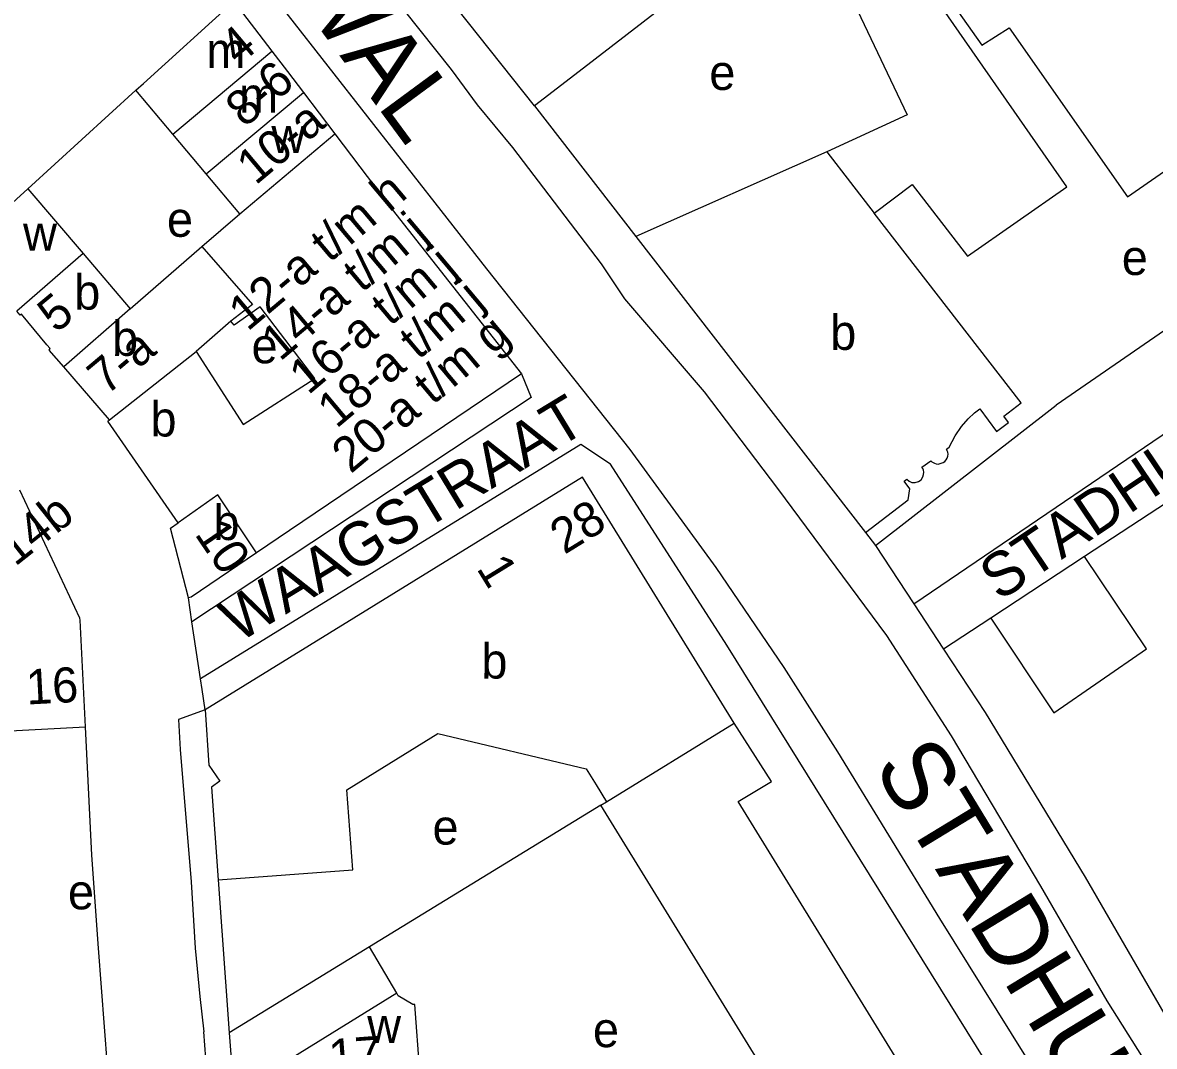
# Model space of a CAD drawing. Extents: x 160673 to 161924, y 382258 to 384145.
# Drawn here: x 161318.4 to 161447.5, y 382888.8 to 383005.6 of the extents above; entities that cross this region are included whole.
import ezdxf

# ---------------------------------------------------------------- set-up
doc = ezdxf.new("R2010")
doc.units = 0
for name, color, linetype in [('BLT_Basislijn', 7, 'Continuous'), ('BLT_Bebouwing', 7, 'Continuous'), ('BLT_Centroide', 7, 'Continuous'), ('BLT_Huisnummer', 7, 'Continuous'), ('BLT_Huisnummer_ tussenligend', 7, 'Continuous'), ('BLT_Huisnummer_reeks', 7, 'Continuous'), ('BLT_Onderverdeling_panden', 7, 'Continuous'), ('BLT_Straatnaam', 7, 'Continuous'), ('BLT_Straatnaam_hoofdweg', 7, 'Continuous')]:
    doc.layers.add(name, color=color, linetype=linetype)

msp = doc.modelspace()

# ---------------------------------------------------------------- linework, layer by layer
at = {"layer": 'BLT_Basislijn'}
for p, q in [((161376.8, 382996.09), (161367.97, 383007.22)), ((161420.08, 382939.26), (161492.74, 382988.68)), ((161415.71, 382945.94), (161436.33, 382961.95)), ((161414.58, 382947.4), (161415.71, 382945.94)), ((161415.71, 382945.94), (161420.08, 382939.26)), ((161439.55, 382944.66), (161428.86, 382937.65)), ((161337.74, 382937.22), (161337.33, 382939.95)), ((161420.08, 382939.26), (161423.46, 382934.11)), ((161338.72, 382930.7), (161337.74, 382937.22)), ((161428.86, 382937.65), (161423.46, 382934.11)), ((161338.9, 382929.5), (161338.72, 382930.7)), ((161339.25, 382927.17), (161338.9, 382929.5)), ((161384.39, 382916.3), (161357.99, 382900.14)), ((161340.74, 382907.78), (161342, 382890.33)), ((161357.99, 382900.14), (161342, 382890.33)), ((161361.1, 382894.85), (161357.99, 382900.14)), ((161338.66, 382894.47), (161339.09, 382890.45)), ((161339.67, 382883.24), (161339.09, 382890.45)), ((161342, 382890.33), (161342.35, 382885.48))]:
    msp.add_line(p, q, dxfattribs=at)
for points in [[(161327.06, 383051.02), (161340.89, 383033.78), (161345.71, 383027.39), (161367.29, 383000.24), (161370.29, 382996.19), (161374.32, 382991.32), (161384.42, 382978.06), (161387.07, 382974.07)], [(161319.1, 383044.02), (161329.09, 383031.39), (161344.2, 383012.2), (161371.35, 382977.49), (161387.69, 382956.87)], [(161415.57, 382983.83), (161419.89, 382987.09), (161426.21, 382978.94), (161437.55, 382986.83), (161417.15, 383016.16), (161416.86, 383017.52), (161417.04, 383018.52), (161417.62, 383019.45), (161418.51, 383020.31), (161420, 383021.17)], [(161407.61, 383019.7), (161419.32, 382995.05), (161410.14, 382990.82)], [(161400.65, 383014.5), (161381.9, 383000), (161376.8, 382996.09)], [(161454.27, 382992.55), (161467.31, 383001.83), (161476.08, 382989.35), (161436.33, 382961.95)], [(161376.8, 382996.09), (161388.37, 382981.18)], [(161387.07, 382974.07), (161396.16, 382963.45), (161404.53, 382952.42), (161416.98, 382935.67), (161424.33, 382924.23), (161434.54, 382907.07)], [(161484.4, 382975.08), (161476.64, 382969.98), (161470.56, 382965.68), (161466.56, 382963.16), (161452.07, 382953.28), (161449.02, 382950.87), (161439.55, 382944.66)], [(161375.34, 382965.52), (161376.43, 382962.82), (161337.74, 382937.22)], [(161434.31, 382877.39), (161398.76, 382934.55), (161385.47, 382955.19), (161382.08, 382957.45), (161338.72, 382930.7)], [(161387.69, 382956.87), (161397.49, 382943.43), (161405.24, 382931.99), (161411.37, 382922.39), (161423, 382903.39), (161434.44, 382885), (161449.34, 382860.28)], [(161428.86, 382937.65), (161436.04, 382926.83), (161446.6, 382934.15), (161439.55, 382944.66)], [(161423.46, 382934.11), (161428.21, 382926.88), (161439.64, 382908.09)], [(161339.25, 382927.17), (161336.21, 382926.06), (161336.41, 382922.64), (161337.67, 382907.55), (161338.12, 382900), (161338.66, 382894.47)], [(161328.11, 382886.52), (161327.08, 382900), (161326.32, 382910.59), (161325.59, 382925.25)], [(161434.54, 382907.07), (161442.09, 382893.99), (161451.48, 382879.08), (161459.65, 382865.39), (161468.43, 382851.91)], [(161439.64, 382908.09), (161449.44, 382891.13), (161461.28, 382871.73), (161473.12, 382851.91)]]:
    msp.add_lwpolyline(points, dxfattribs=at)
at = {"layer": 'BLT_Bebouwing'}
for p, q in [((161342.51, 383007.98), (161346.85, 383002.32)), ((161331.36, 382997.86), (161319.02, 382986.62)), ((161335.57, 382992.85), (161331.36, 382997.86)), ((161350.45, 382997.61), (161354.04, 382992.88)), ((161339.38, 382988.31), (161335.57, 382992.85)), ((161444.45, 382985.71), (161454.27, 382992.55)), ((161410.14, 382990.82), (161388.37, 382981.18)), ((161410.14, 382990.82), (161415.57, 382983.83)), ((161343.19, 382983.77), (161339.38, 382988.31)), ((161319.02, 382986.62), (161325.33, 382979.24)), ((161338.87, 382980.02), (161343.19, 382983.77)), ((161388.37, 382981.18), (161414.58, 382947.4)), ((161325.33, 382979.24), (161330.71, 382972.92)), ((161330.71, 382972.92), (161338.87, 382980.02)), ((161328.34, 382960.25), (161323.12, 382966.29)), ((161375.34, 382965.52), (161348.87, 382947.62)), ((161382.27, 382953.72), (161339.25, 382927.17)), ((161399.58, 382925.67), (161382.27, 382953.72)), ((161325.59, 382925.25), (161324.98, 382937.39)), ((161339.25, 382927.17), (161339.67, 382920.86)), ((161315.06, 382924.69), (161325.59, 382925.25)), ((161383.85, 382918.61), (161385.03, 382916.7)), ((161384.39, 382916.3), (161385.03, 382916.7)), ((161340.74, 382907.78), (161356.08, 382908.91)), ((161363.82, 382884.73), (161363.17, 382893.58))]:
    msp.add_line(p, q, dxfattribs=at)
for points in [[(161420, 383021.17), (161426, 383012.5), (161422.77, 383010.19), (161427.84, 383002.98), (161430.96, 383004.98), (161444.45, 382985.71)], [(161346.85, 383002.32), (161348.63, 383000), (161350.45, 382997.61)], [(161354.04, 382992.88), (161360.58, 382984.27), (161375.34, 382965.52)], [(161414.58, 382947.4), (161419.43, 382951.12), (161419.61, 382952.38), (161418.96, 382953.26), (161419.28, 382953.5), (161419.54, 382953.26), (161419.84, 382953.13), (161420.23, 382953.1), (161420.63, 382953.22), (161420.9, 382953.41), (161421.11, 382953.74), (161421.2, 382954.01), (161421.21, 382954.29), (161421.17, 382954.53), (161421.09, 382954.7), (161421, 382954.85), (161422.02, 382955.6), (161422.14, 382955.48), (161422.29, 382955.38), (161422.45, 382955.3), (161422.63, 382955.24), (161422.87, 382955.22), (161423.1, 382955.26), (161423.41, 382955.38), (161423.6, 382955.51), (161423.76, 382955.69), (161423.88, 382955.9), (161423.95, 382956.12), (161423.98, 382956.35), (161423.95, 382956.57), (161423.9, 382956.74), (161423.86, 382956.85), (161423.81, 382956.93), (161424.12, 382957.16), (161424.79, 382958.43), (161425.53, 382959.51), (161426.27, 382960.37), (161427.01, 382961.07), (161427.62, 382961.52), (161429.51, 382958.92), (161430.87, 382959.95), (161430.33, 382960.66), (161432.33, 382962.19), (161415.57, 382983.83)], [(161343.6, 382959.73), (161351.76, 382964.97), (161345.52, 382973.14), (161342.54, 382971.07), (161342.17, 382971.5)], [(161321.2, 382968.81), (161318.29, 382972.3), (161318.16, 382972.2), (161317.77, 382972.66)], [(161342.17, 382971.5), (161338.21, 382968.04)], [(161323.12, 382966.29), (161321.46, 382968.22), (161321.56, 382968.38), (161321.2, 382968.81)], [(161338.21, 382968.04), (161343.6, 382959.73)], [(161336.17, 382948.5), (161328.13, 382960.11), (161328.34, 382960.25)], [(161324.98, 382937.39), (161324.96, 382937.64), (161318.11, 382952.23)], [(161337.33, 382939.95), (161335.3, 382947.9), (161336.17, 382948.5)], [(161348.87, 382947.62), (161345.09, 382945.07)], [(161345.09, 382945.07), (161337.64, 382940.03), (161337.33, 382939.95)], [(161425.19, 382885.41), (161420.86, 382882.9), (161400.06, 382916.74), (161403.83, 382919.01), (161399.58, 382925.67)], [(161356.08, 382908.91), (161355.4, 382918.07), (161365.78, 382924.47), (161382.7, 382920.46), (161383.85, 382918.61)], [(161339.67, 382920.86), (161340.92, 382919.03), (161339.96, 382918.37), (161340.74, 382907.78)], [(161394.29, 382830.83), (161378.77, 382855.98), (161378.13, 382865.54), (161405.34, 382882.28), (161384.39, 382916.3)], [(161361.1, 382894.85), (161349.25, 382887.52), (161349.32, 382886.57)], [(161363.17, 382893.58), (161362.93, 382893.57), (161361.28, 382894.57), (161361.1, 382894.85)]]:
    msp.add_lwpolyline(points, dxfattribs=at)
at = {"layer": 'BLT_Onderverdeling_panden'}
for p, q in [((161332.2, 382998.63), (161342.51, 383007.98)), ((161335.57, 382992.85), (161346.85, 383002.32)), ((161339.38, 382988.31), (161350.45, 382997.61)), ((161343.19, 382983.77), (161354.04, 382992.88)), ((161311.38, 382979.68), (161319.02, 382986.62)), ((161325.33, 382979.24), (161317.77, 382972.66)), ((161330.71, 382972.92), (161323.12, 382966.29)), ((161328.34, 382960.25), (161338.21, 382968.04)), ((161385.03, 382916.7), (161399.58, 382925.67))]:
    msp.add_line(p, q, dxfattribs=at)
for points in [[(161331.36, 382997.86), (161332.2, 382998.63)], [(161338.87, 382980.02), (161344.63, 382973.43), (161342.17, 382971.5)], [(161345.09, 382945.07), (161340.7, 382951.69), (161336.17, 382948.5)]]:
    msp.add_lwpolyline(points, dxfattribs=at)

# ---------------------------------------------------------------- texts
at = {"layer": 'BLT_Centroide'}
for s, p in [('m', (161339.38, 383000.41)), ('e', (161396.75, 382997.89)), ('m', (161343.11, 382995.31)), ('w', (161346.81, 382990.69)), ('e', (161334.89, 382981.14)), ('w', (161318.48, 382979.56)), ('e', (161443.8, 382976.78)), ('b', (161324.31, 382972.84)), ('b', (161328.63, 382967.56)), ('b', (161410.54, 382968.24)), ('e', (161344.54, 382966.71)), ('b', (161333.01, 382958.36)), ('b', (161340.19, 382946.55)), ('b', (161370.75, 382930.75)), ('e', (161365.18, 382911.81)), ('e', (161323.6, 382904.42)), ('w', (161357.73, 382889.19)), ('e', (161383.48, 382888.7))]:
    msp.add_text(s, height=4, dxfattribs=at).set_placement(p)
at = {"layer": 'BLT_Huisnummer'}
for s, rotation, p in [('4', 40.0182, (161343.07, 383000.59)), ('10', 304.145, (161337.97, 382947.23))]:
    msp.add_text(s, height=4, rotation=rotation, dxfattribs=at).set_placement(p)
at = {"layer": 'BLT_Huisnummer_ tussenligend'}
msp.add_text('5', height=4, rotation=39.7924, dxfattribs=at).set_placement((161322.26, 382970.06))
at = {"layer": 'BLT_Huisnummer_reeks'}
for s, rotation, p in [('8-6', 40.0182, (161343.73, 382993.5)), ('10-a', 40.0169, (161345, 382986.95)), ('12-a t/m h', 40.0169, (161344.08, 382970.27)), ('14-a t/m j', 40.0169, (161347.78, 382966.85)), ('16-a t/m j', 40.0169, (161351, 382963.02)), ('18-a t/m j', 40.0169, (161354.21, 382959.19)), ('20-a t/m g', 40.0169, (161355.85, 382954.04)), ('7-a', 39.9477, (161327.97, 382962.96)), ('14a-14b', 38.3869, (161309.17, 382936.81)), ('28', 31.6759, (161380.22, 382944.84)), ('1', 301.6756, (161370.13, 382943.32)), ('16', 3.0268, (161318.92, 382927.78)), ('17', 4.2696, (161353.49, 382885.58))]:
    msp.add_text(s, height=4, rotation=rotation, dxfattribs=at).set_placement(p)
at = {"layer": 'BLT_Straatnaam'}
for s, height, rotation, p in [('BEGIJNENHOF', 4.9999, 305.2357, (161437.35, 383041.52)), ('STADHUISPLEIN', 5, 33.9383, (161429.83, 382939.49)), ('WAAGSTRAAT', 5, 31.3527, (161343.03, 382934.74))]:
    msp.add_text(s, height=height, rotation=rotation, dxfattribs=at).set_placement(p)
at = {"layer": 'BLT_Straatnaam_hoofdweg'}
for s, rotation, p in [('WAL', 306.3845, (161348.54, 383009.96)), ('STADHUISPLEIN', 301.3164, (161415.36, 382920.7))]:
    msp.add_text(s, height=8, rotation=rotation, dxfattribs=at).set_placement(p)

doc.saveas('drawing.dxf')
